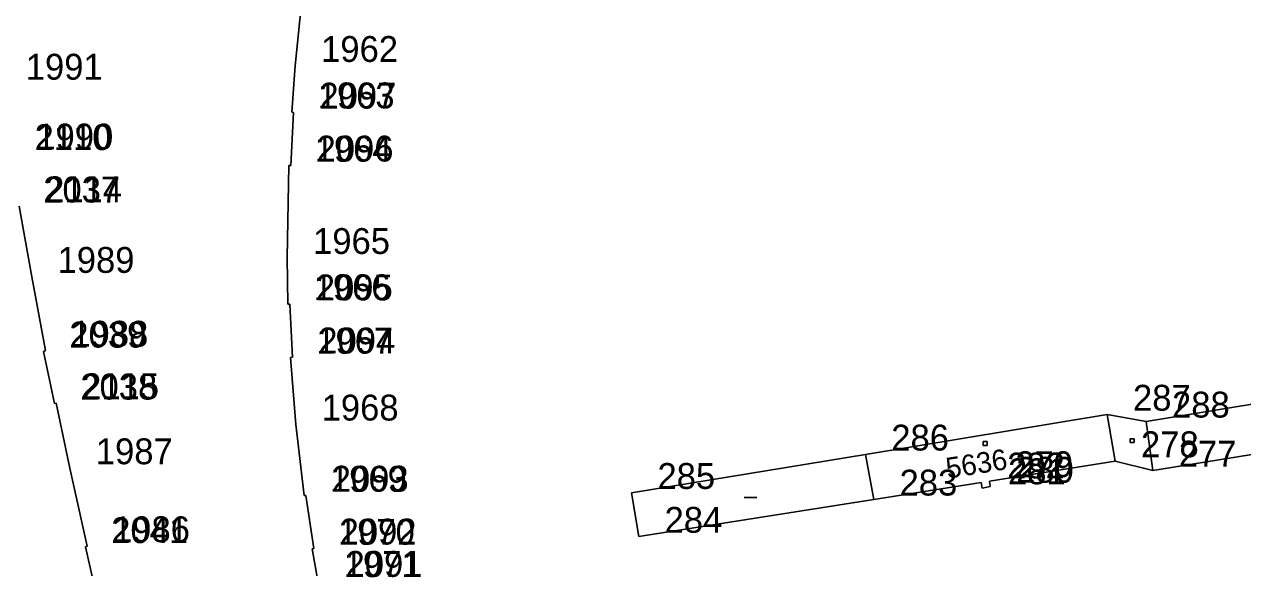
# Model space of a CAD drawing. Extents: x -822293 to -820259, y -1071573 to -1068794.
# Drawn here: x -821466.4 to -821372.2, y -1070159.3 to -1070117.3 of the extents above; entities that cross this region are included whole.
import ezdxf

# ---------------------------------------------------------------- set-up
doc = ezdxf.new("R2010")
doc.units = 0
for name, color, linetype in [('Vrstva 11', 7, 'Continuous'), ('Vrstva 2', 7, 'Continuous'), ('Vrstva 3', 7, 'Continuous'), ('Vrstva 6', 7, 'Continuous'), ('Vrstva 8', 7, 'Continuous'), ('Vrstva 9', 7, 'Continuous')]:
    doc.layers.add(name, color=color, linetype=linetype)

# ---------------------------------------------------------------- blocks, each defined once
blk = doc.blocks.new('Z403')
at = {"layer": 'Vrstva 2'}
blk.add_line((-50, 0), (50, 0), dxfattribs=at)
blk = doc.blocks.new('Z402')
at = {"layer": 'Vrstva 2'}
for p, q in [((-10, 10), (20, 10)), ((-10, -20), (-10, 10)), ((20, 10), (20, -20)), ((20, -20), (-10, -20))]:
    blk.add_line(p, q, dxfattribs=at)

msp = doc.modelspace()

# ---------------------------------------------------------------- linework, layer by layer
at = {"layer": 'Vrstva 2'}
for p, q in [((-821379.63, -1070147.99), (-821356.8, -1070144.26)), ((-821401.35, -1070150.54), (-821382.65, -1070147.46)), ((-821382.65, -1070147.46), (-821379.63, -1070147.99)), ((-821356.34, -1070148.08), (-821379.11, -1070151.78)), ((-821419.44, -1070153.51), (-821401.35, -1070150.54)), ((-821382.03, -1070151.06), (-821391.75, -1070152.6)), ((-821379.11, -1070151.78), (-821382.03, -1070151.06)), ((-821392.39, -1070152.7), (-821400.71, -1070154.02)), ((-821392.32, -1070153.15), (-821392.39, -1070152.7)), ((-821391.75, -1070152.6), (-821391.69, -1070153.03)), ((-821418.89, -1070156.9), (-821419.44, -1070153.51)), ((-821391.69, -1070153.03), (-821392.32, -1070153.15)), ((-821400.71, -1070154.02), (-821418.89, -1070156.9))]:
    msp.add_line(p, q, dxfattribs=at)
at = {"layer": 'Vrstva 3'}
for p, q in [((-821444.74, -1070113.36), (-821445.46, -1070120.49)), ((-821445.46, -1070120.49), (-821445.73, -1070124.08)), ((-821445.59, -1070124.1), (-821445.81, -1070128.19)), ((-821445.73, -1070124.08), (-821445.59, -1070124.1)), ((-821445.96, -1070128.21), (-821446.08, -1070135.34)), ((-821445.81, -1070128.19), (-821445.96, -1070128.21)), ((-821466.81, -1070131.34), (-821465.85, -1070136.8)), ((-821446.08, -1070135.34), (-821446.04, -1070138.91)), ((-821465.85, -1070136.8), (-821464.78, -1070142.51)), ((-821446.04, -1070138.91), (-821445.87, -1070138.93)), ((-821445.87, -1070138.93), (-821445.68, -1070143.03)), ((-821464.78, -1070142.51), (-821464.94, -1070142.58)), ((-821464.94, -1070142.58), (-821464.09, -1070146.6)), ((-821445.68, -1070143.03), (-821445.84, -1070143.05)), ((-821445.84, -1070143.05), (-821445.42, -1070148.22)), ((-821464.09, -1070146.6), (-821463.95, -1070146.57)), ((-821463.95, -1070146.57), (-821462.89, -1070151.6)), ((-821445.42, -1070148.22), (-821444.78, -1070153.73)), ((-821382.65, -1070147.46), (-821382.03, -1070151.06)), ((-821379.63, -1070147.99), (-821379.11, -1070151.78)), ((-821400.71, -1070154.02), (-821401.35, -1070150.54)), ((-821462.89, -1070151.6), (-821461.56, -1070157.63)), ((-821444.78, -1070153.73), (-821444.64, -1070153.72)), ((-821444.64, -1070153.72), (-821444.03, -1070157.81)), ((-821461.56, -1070157.63), (-821461.7, -1070157.7)), ((-821461.7, -1070157.7), (-821460.77, -1070161.7)), ((-821444.03, -1070157.81), (-821444.16, -1070157.83)), ((-821444.16, -1070157.83), (-821443.72, -1070160.32))]:
    msp.add_line(p, q, dxfattribs=at)
at = {"layer": 'Vrstva 8'}
for p, q in [((-821445.46, -1070120.49), (-821445.46, -1070120.49)), ((-821445.73, -1070124.08), (-821445.73, -1070124.08)), ((-821445.59, -1070124.1), (-821445.59, -1070124.1)), ((-821445.96, -1070128.21), (-821445.96, -1070128.21)), ((-821445.81, -1070128.19), (-821445.81, -1070128.19)), ((-821446.08, -1070135.34), (-821446.08, -1070135.34)), ((-821465.85, -1070136.8), (-821465.85, -1070136.8)), ((-821446.04, -1070138.91), (-821446.04, -1070138.91)), ((-821445.87, -1070138.93), (-821445.87, -1070138.93)), ((-821464.94, -1070142.58), (-821464.94, -1070142.58)), ((-821464.78, -1070142.51), (-821464.78, -1070142.51)), ((-821445.84, -1070143.05), (-821445.84, -1070143.05)), ((-821445.68, -1070143.03), (-821445.68, -1070143.03)), ((-821464.09, -1070146.6), (-821464.09, -1070146.6)), ((-821463.95, -1070146.57), (-821463.95, -1070146.57)), ((-821445.42, -1070148.22), (-821445.42, -1070148.22)), ((-821382.65, -1070147.46), (-821382.65, -1070147.46)), ((-821379.63, -1070147.99), (-821379.63, -1070147.99)), ((-821401.35, -1070150.54), (-821401.35, -1070150.54)), ((-821382.03, -1070151.06), (-821382.03, -1070151.06)), ((-821462.89, -1070151.6), (-821462.89, -1070151.6)), ((-821379.11, -1070151.78), (-821379.11, -1070151.78)), ((-821392.39, -1070152.7), (-821392.39, -1070152.7)), ((-821391.75, -1070152.6), (-821391.75, -1070152.6)), ((-821444.78, -1070153.73), (-821444.78, -1070153.73)), ((-821444.64, -1070153.72), (-821444.64, -1070153.72)), ((-821419.44, -1070153.51), (-821419.44, -1070153.51)), ((-821392.32, -1070153.15), (-821392.32, -1070153.15)), ((-821391.69, -1070153.03), (-821391.69, -1070153.03)), ((-821400.71, -1070154.02), (-821400.71, -1070154.02)), ((-821461.56, -1070157.63), (-821461.56, -1070157.63)), ((-821418.89, -1070156.9), (-821418.89, -1070156.9)), ((-821461.7, -1070157.7), (-821461.7, -1070157.7)), ((-821444.16, -1070157.83), (-821444.16, -1070157.83)), ((-821444.03, -1070157.81), (-821444.03, -1070157.81))]:
    msp.add_line(p, q, dxfattribs=at)

# ---------------------------------------------------------------- block references
at = {"layer": 'Vrstva 11', "xscale": 0.01, "yscale": 0.01}
for name, p in [('Z402', (-821392.13, -1070149.65)), ('Z402', (-821380.77, -1070149.43)), ('Z403', (-821410.24, -1070153.88))]:
    msp.add_blockref(name, p, dxfattribs=at)

# ---------------------------------------------------------------- texts
at = {"layer": 'Vrstva 6'}
msp.add_text('5636', height=1.6, rotation=9, dxfattribs=at).set_placement((-821394.988, -1070152.414))
at = {"layer": 'Vrstva 9'}
for s, p in [('1962', (-821443.46, -1070120.19)), ('1991', (-821466.31, -1070121.56)), ('1963', (-821443.73, -1070123.78)), ('2097', (-821443.59, -1070123.8)), ('2110', (-821465.63, -1070127.01)), ('1990', (-821465.49, -1070126.96)), ('1964', (-821443.96, -1070127.91)), ('2096', (-821443.81, -1070127.89)), ('2037', (-821464.96, -1070131.06)), ('2114', (-821464.81, -1070131.04)), ('1965', (-821444.08, -1070135.04)), ('1989', (-821463.85, -1070136.5)), ('1966', (-821444.04, -1070138.61)), ('2095', (-821443.87, -1070138.63)), ('2039', (-821462.94, -1070142.28)), ('1988', (-821462.78, -1070142.21)), ('2094', (-821443.68, -1070142.73)), ('1967', (-821443.84, -1070142.75)), ('2038', (-821462.09, -1070146.3)), ('2115', (-821461.95, -1070146.27)), ('287', (-821380.65, -1070147.16)), ('1968', (-821443.42, -1070147.92)), ('288', (-821377.63, -1070147.69)), ('286', (-821399.35, -1070150.24)), ('278', (-821380.03, -1070150.76)), ('1987', (-821460.89, -1070151.3)), ('277', (-821377.11, -1070151.48)), ('282', (-821390.39, -1070152.4)), ('281', (-821390.32, -1070152.85)), ('279', (-821389.75, -1070152.3)), ('280', (-821389.69, -1070152.73)), ('1969', (-821442.78, -1070153.43)), ('2093', (-821442.64, -1070153.42)), ('285', (-821417.44, -1070153.21)), ('283', (-821398.71, -1070153.72)), ('284', (-821416.89, -1070156.6)), ('2041', (-821459.7, -1070157.4)), ('1986', (-821459.56, -1070157.33)), ('1970', (-821442.16, -1070157.53)), ('2092', (-821442.03, -1070157.51)), ('1971', (-821441.72, -1070160.02)), ('2091', (-821441.57, -1070160.01))]:
    msp.add_text(s, height=2, dxfattribs=at).set_placement(p)

doc.saveas('drawing.dxf')
